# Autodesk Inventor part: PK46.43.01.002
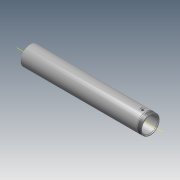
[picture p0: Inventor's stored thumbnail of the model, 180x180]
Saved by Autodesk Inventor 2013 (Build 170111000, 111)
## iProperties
Shininess: 64.0
Length Units: 11269
Angle Units: 11279
Time Units: 11290
Mass Units: 11283
Length Display Precision: 3
Angle Display Precision: 2
Compacted: True
Part Number: PK46.43.01.002
Document SubType Name: Modeling
Created: 2004-11
Material: Steel, High Strength Low Alloy
Designer: ELarisa
Manufacturer: Standard
Standards Organization: Custom
Density: 7.84 g/cm^3
Density: 0.0
Volumn: 0.0
Area: 0.0
PropertySet Name: Model Information
Control State: 0
Master: False
Checked Out: False
Checked Out Date: 2008-10-09
Last Check In Date: 2008-10-09
Author: ELarisa
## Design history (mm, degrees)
sketch "Эскиз1"
  geometry: L1 (-897.858, -57.258)-(-897.858, 6.242); L2 (-897.858, 6.242)-(-893.308, 18.742); L3 (-893.308, 18.742)-(30.142, 18.742); L4 (30.142, 18.742)-(30.142, 16.242); L5 (30.142, 16.242)-(35.142, 16.242); L6 (35.142, 16.242)-(36.642, 17.742); L7 (36.642, 17.742)-(63.142, 17.742); L8 (63.142, 17.742)-(65.142, 15.742); L9 (65.142, 15.742)-(65.142, -57.258); L10 (65.142, -57.258)-(-897.858, -57.258); L11 (-897.858, 5.242)-(53.142, 5.242); L12 (53.142, 5.242)-(58.142, 6.582); L13 (58.142, 6.582)-(58.142, 9.742); L14 (58.142, 9.742)-(65.142, 9.742)
  constraints: 28 end point, 6 parallel, 3 perpendicular, 2 point on line, 1 vertical
  dimensions: "d0" = 963 distance of L9.end L1.start; "d3" = 5 horizontal distance of L11.end L12.end; "d4" = 76 distance between parallel lines of L10 L3; "d5" = 75 distance between parallel lines of L10 L7; "d6" = 135 deg angle of L7 L6; "d7" = 135 deg angle of L8 L7 (derived); "d8" = 2 horizontal distance of L7.end L8.end; "d9" = 5 distance of L4.end L5.end; "d10" = 35 distance between parallel lines of L4 L9; "d11" = 1.5 distance from line of L6.end L5; "d12" = 62.5 distance between parallel lines of L10 L11; "d13" = 7 distance of L13.end L14.end; "d14" = 165 deg angle of L12 L11; "d15" = 67 distance between parallel lines of L10 L14; "d17" = 63.5 distance of L1.start L1.end; "d18" = 20 deg angle of L2 L1
revolve "Вращение1" sketch "Эскиз1" stored, may be unused: angle "d19" = 90 deg
feature "Резьба1" dims "d20" = 10, "d21" = 0
node "РабОсь1"
node "РабПлоскость1"
sketch "Эскиз2"
  geometry: L1 (-1090.458, -57.258)-(257.742, -57.258) reference; L2 (65.142, -124.258)-(65.142, 9.742) reference; 1 further point
  dimensions: "d23" = 0 distance from line of L1 point (3.142, -57.258); "d24" = 62 distance from line of L2 point (3.142, -57.258)
hole "Отверстие1" sketch "Эскиз2" diameter "d25" = 20; stored, may be unused: countersink angle "d29" = 82 deg, drill point angle "d31" = 118 deg; dims "d26" = 6, "d27" = 36, "d28" = 5, "d30" = 20
body "Solid1"
other parameters: "d22" = 76
